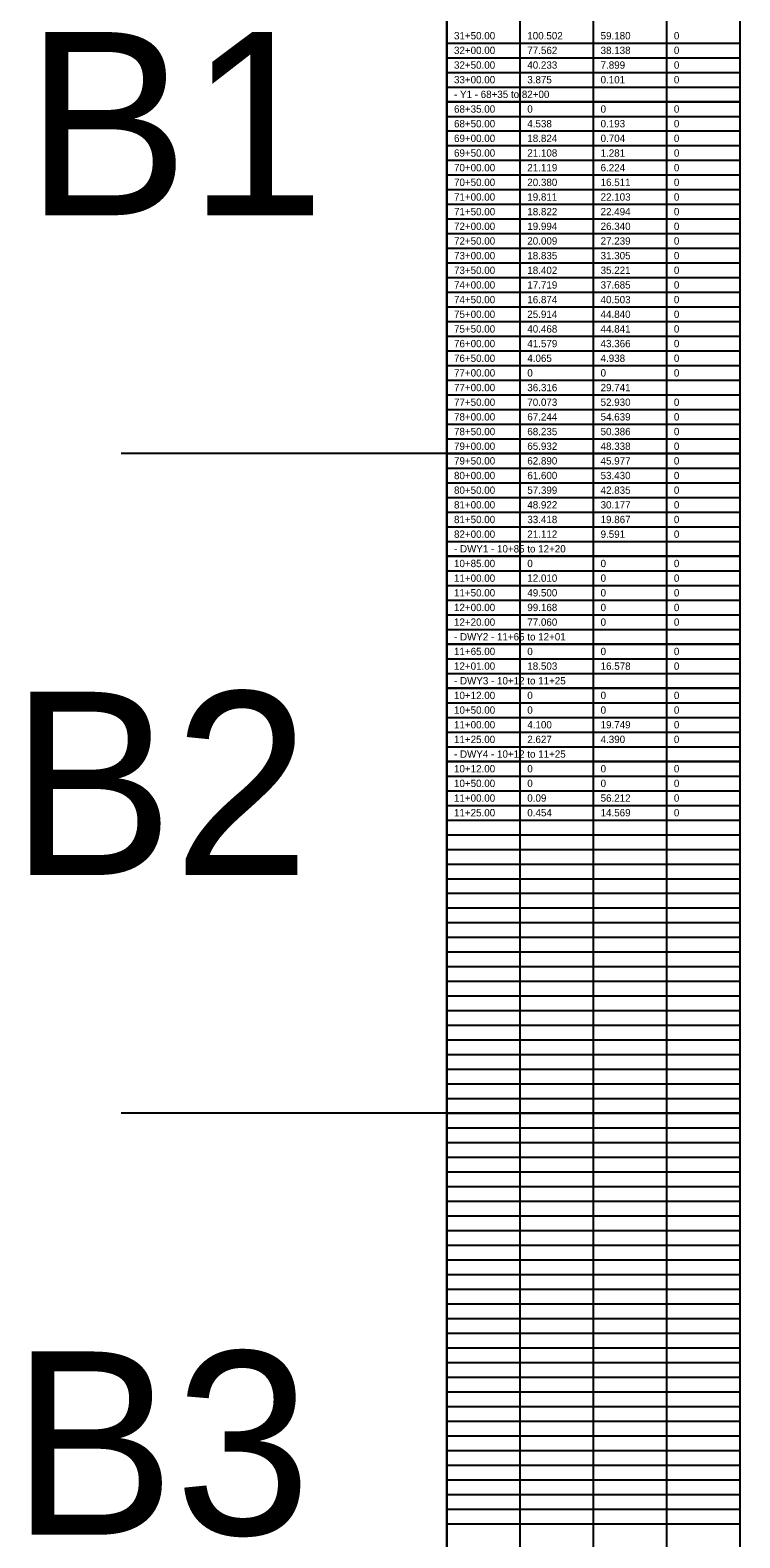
# Model space of a CAD drawing. Extents: x -124 to 80, y -10800 to 19.
# Drawn here: x -113.7 to 80, y -1195.9 to -784.5 of the extents above; entities that cross this region are included whole.
import ezdxf

# ---------------------------------------------------------------- set-up
doc = ezdxf.new("R2010")
doc.units = 0
for name, color, linetype in [('Prop Shade Light', 7, 'Continuous'), ('Prop XSC Text', 7, 'Continuous'), ('Scratch_Level_1', 7, 'Continuous'), ('Scratch_Level_3', 7, 'Continuous'), ('Sheet Clip Boundary CELL', 7, 'Continuous')]:
    doc.layers.add(name, color=color, linetype=linetype)

msp = doc.modelspace()

# ---------------------------------------------------------------- linework, layer by layer
at = {"layer": 'Prop Shade Light'}
for points in [[(0, -800), (80, -800), (80, -804), (0, -804)], [(0, -924), (80, -924), (80, -928), (0, -928)], [(0, -948), (80, -948), (80, -952), (0, -952)], [(0, -960), (80, -960), (80, -964), (0, -964)], [(0, -980), (80, -980), (80, -984), (0, -984)]]:
    msp.add_lwpolyline(points, close=True, dxfattribs=at)
at = {"layer": 'Scratch_Level_1'}
for p, q in [((0, 0), (0, -6480)), ((20, 0), (20, -6480)), ((40, 0), (40, -6480)), ((60, 0), (60, -6480)), ((80, 0), (80, -6480)), ((0, -788), (80, -788)), ((0, -792), (80, -792)), ((0, -796), (80, -796)), ((0, -800), (80, -800)), ((0, -804), (80, -804)), ((0, -808), (80, -808)), ((0, -812), (80, -812)), ((0, -816), (80, -816)), ((0, -820), (80, -820)), ((0, -824), (80, -824)), ((0, -828), (80, -828)), ((0, -832), (80, -832)), ((0, -836), (80, -836)), ((0, -840), (80, -840)), ((0, -844), (80, -844)), ((0, -848), (80, -848)), ((0, -852), (80, -852)), ((0, -856), (80, -856)), ((0, -860), (80, -860)), ((0, -864), (80, -864)), ((0, -868), (80, -868)), ((0, -872), (80, -872)), ((0, -876), (80, -876)), ((0, -880), (80, -880)), ((0, -884), (80, -884)), ((0, -888), (80, -888)), ((0, -892), (80, -892)), ((0, -896), (80, -896)), ((0, -900), (-88.81, -900)), ((0, -900), (80, -900)), ((0, -904), (80, -904)), ((0, -908), (80, -908)), ((0, -912), (80, -912)), ((0, -916), (80, -916)), ((0, -920), (80, -920)), ((0, -924), (80, -924)), ((0, -928), (80, -928)), ((0, -932), (80, -932)), ((0, -936), (80, -936)), ((0, -940), (80, -940)), ((0, -944), (80, -944)), ((0, -948), (80, -948)), ((0, -952), (80, -952)), ((0, -956), (80, -956)), ((0, -960), (80, -960)), ((0, -964), (80, -964)), ((0, -968), (80, -968)), ((0, -972), (80, -972)), ((0, -976), (80, -976)), ((0, -980), (80, -980)), ((0, -984), (80, -984)), ((0, -988), (80, -988)), ((0, -992), (80, -992)), ((0, -996), (80, -996)), ((0, -1000), (80, -1000)), ((0, -1004), (80, -1004)), ((0, -1008), (80, -1008)), ((0, -1012), (80, -1012)), ((0, -1016), (80, -1016)), ((0, -1020), (80, -1020)), ((0, -1024), (80, -1024)), ((0, -1028), (80, -1028)), ((0, -1032), (80, -1032)), ((0, -1036), (80, -1036)), ((0, -1040), (80, -1040)), ((0, -1044), (80, -1044)), ((0, -1048), (80, -1048)), ((0, -1052), (80, -1052)), ((0, -1056), (80, -1056)), ((0, -1060), (80, -1060)), ((0, -1064), (80, -1064)), ((0, -1068), (80, -1068)), ((0, -1072), (80, -1072)), ((0, -1076), (80, -1076)), ((0, -1080), (-88.81, -1080)), ((0, -1080), (80, -1080)), ((0, -1084), (80, -1084)), ((0, -1088), (80, -1088)), ((0, -1092), (80, -1092)), ((0, -1096), (80, -1096)), ((0, -1100), (80, -1100)), ((0, -1104), (80, -1104)), ((0, -1108), (80, -1108)), ((0, -1112), (80, -1112)), ((0, -1116), (80, -1116)), ((0, -1120), (80, -1120)), ((0, -1124), (80, -1124)), ((0, -1128), (80, -1128)), ((0, -1132), (80, -1132)), ((0, -1136), (80, -1136)), ((0, -1140), (80, -1140)), ((0, -1144), (80, -1144)), ((0, -1148), (80, -1148)), ((0, -1152), (80, -1152)), ((0, -1156), (80, -1156)), ((0, -1160), (80, -1160)), ((0, -1164), (80, -1164)), ((0, -1168), (80, -1168)), ((0, -1172), (80, -1172)), ((0, -1176), (80, -1176)), ((0, -1180), (80, -1180)), ((0, -1184), (80, -1184)), ((0, -1188), (80, -1188)), ((0, -1192), (80, -1192))]:
    msp.add_line(p, q, dxfattribs=at)
at = {"layer": 'Sheet Clip Boundary CELL'}
for points in [[(0, -720), (80, -720), (80, -900), (0, -900)], [(0, -900), (80, -900), (80, -1080), (0, -1080)], [(0, -1080), (80, -1080), (80, -1260), (0, -1260)]]:
    msp.add_lwpolyline(points, close=True, dxfattribs=at)

# ---------------------------------------------------------------- texts
at = {"layer": 'Prop XSC Text'}
for s, p in [('31+50.00', (2, -787)), ('100.502', (22, -787)), ('59.180', (42, -787)), ('0', (62, -787)), ('32+00.00', (2, -791)), ('77.562', (22, -791)), ('38.138', (42, -791)), ('0', (62, -791)), ('32+50.00', (2, -795)), ('40.233', (22, -795)), ('7.899', (42, -795)), ('0', (62, -795)), ('33+00.00', (2, -799)), ('3.875', (22, -799)), ('0.101', (42, -799)), ('0', (62, -799)), ('- Y1 - 68+35 to 82+00', (2, -803)), ('68+35.00', (2, -807)), ('0', (22, -807)), ('0', (42, -807)), ('0', (62, -807)), ('68+50.00', (2, -811)), ('4.538', (22, -811)), ('0.193', (42, -811)), ('0', (62, -811)), ('69+00.00', (2, -815)), ('18.824', (22, -815)), ('0.704', (42, -815)), ('0', (62, -815)), ('69+50.00', (2, -819)), ('21.108', (22, -819)), ('1.281', (42, -819)), ('0', (62, -819)), ('70+00.00', (2, -823)), ('21.119', (22, -823)), ('6.224', (42, -823)), ('0', (62, -823)), ('70+50.00', (2, -827)), ('20.380', (22, -827)), ('16.511', (42, -827)), ('0', (62, -827)), ('71+00.00', (2, -831)), ('19.811', (22, -831)), ('22.103', (42, -831)), ('0', (62, -831)), ('71+50.00', (2, -835)), ('18.822', (22, -835)), ('22.494', (42, -835)), ('0', (62, -835)), ('72+00.00', (2, -839)), ('19.994', (22, -839)), ('26.340', (42, -839)), ('0', (62, -839)), ('72+50.00', (2, -843)), ('20.009', (22, -843)), ('27.239', (42, -843)), ('0', (62, -843)), ('73+00.00', (2, -847)), ('18.835', (22, -847)), ('31.305', (42, -847)), ('0', (62, -847)), ('73+50.00', (2, -851)), ('18.402', (22, -851)), ('35.221', (42, -851)), ('0', (62, -851)), ('74+00.00', (2, -855)), ('17.719', (22, -855)), ('37.685', (42, -855)), ('0', (62, -855)), ('74+50.00', (2, -859)), ('16.874', (22, -859)), ('40.503', (42, -859)), ('0', (62, -859)), ('75+00.00', (2, -863)), ('25.914', (22, -863)), ('44.840', (42, -863)), ('0', (62, -863)), ('75+50.00', (2, -867)), ('40.468', (22, -867)), ('44.841', (42, -867)), ('0', (62, -867)), ('76+00.00', (2, -871)), ('41.579', (22, -871)), ('43.366', (42, -871)), ('0', (62, -871)), ('76+50.00', (2, -875)), ('4.065', (22, -875)), ('4.938', (42, -875)), ('0', (62, -875)), ('77+00.00', (2, -879)), ('0', (22, -879)), ('0', (42, -879)), ('0', (62, -879)), ('77+00.00', (2, -883)), ('36.316', (22, -883)), ('29.741', (42, -883)), ('77+50.00', (2, -887)), ('70.073', (22, -887)), ('52.930', (42, -887)), ('0', (62, -887)), ('78+00.00', (2, -891)), ('67.244', (22, -891)), ('54.639', (42, -891)), ('0', (62, -891)), ('78+50.00', (2, -895)), ('68.235', (22, -895)), ('50.386', (42, -895)), ('0', (62, -895)), ('79+00.00', (2, -899)), ('65.932', (22, -899)), ('48.338', (42, -899)), ('0', (62, -899)), ('80+00.00', (2, -907)), ('79+50.00', (2, -903)), ('62.890', (22, -903)), ('61.600', (22, -907)), ('45.977', (42, -903)), ('53.430', (42, -907)), ('0', (62, -903)), ('0', (62, -907)), ('80+50.00', (2, -911)), ('57.399', (22, -911)), ('42.835', (42, -911)), ('0', (62, -911)), ('81+00.00', (2, -915)), ('48.922', (22, -915)), ('30.177', (42, -915)), ('0', (62, -915)), ('81+50.00', (2, -919)), ('33.418', (22, -919)), ('19.867', (42, -919)), ('0', (62, -919)), ('82+00.00', (2, -923)), ('21.112', (22, -923)), ('9.591', (42, -923)), ('0', (62, -923)), ('- DWY1 - 10+85 to 12+20 ', (2, -927)), ('10+85.00', (2, -931)), ('0', (22, -931)), ('0', (42, -931)), ('0', (62, -931)), ('11+00.00', (2, -935)), ('12.010', (22, -935)), ('0', (42, -935)), ('0', (62, -935)), ('11+50.00', (2, -939)), ('49.500', (22, -939)), ('0', (42, -939)), ('0', (62, -939)), ('12+00.00', (2, -943)), ('99.168', (22, -943)), ('0', (42, -943)), ('0', (62, -943)), ('12+20.00', (2, -947)), ('77.060', (22, -947)), ('0', (42, -947)), ('0', (62, -947)), ('- DWY2 - 11+65 to 12+01 ', (2, -951)), ('11+65.00', (2, -955)), ('0', (22, -955)), ('0', (42, -955)), ('0', (62, -955)), ('12+01.00', (2, -959)), ('18.503', (22, -959)), ('16.578', (42, -959)), ('0', (62, -959)), ('- DWY3 - 10+12 to 11+25', (2, -963)), ('10+12.00', (2, -967)), ('0', (22, -967)), ('0', (42, -967)), ('0', (62, -967)), ('10+50.00', (2, -971)), ('0', (22, -971)), ('0', (42, -971)), ('0', (62, -971)), ('11+00.00', (2, -975)), ('4.100', (22, -975)), ('19.749', (42, -975)), ('0', (62, -975)), ('11+25.00', (2, -979)), ('2.627', (22, -979)), ('4.390', (42, -979)), ('0', (62, -979)), ('- DWY4 - 10+12 to 11+25 ', (2, -983)), ('10+12.00', (2, -987)), ('0', (22, -987)), ('0', (42, -987)), ('0', (62, -987)), ('10+50.00', (2, -991)), ('0', (22, -991)), ('0', (42, -991)), ('0', (62, -991)), ('11+00.00', (2, -995)), ('0.09', (22, -995)), ('56.212', (42, -995)), ('0', (62, -995)), ('11+25.00', (2, -999)), ('0.454', (22, -999)), ('14.569', (42, -999)), ('0', (62, -999))]:
    msp.add_text(s, height=2, dxfattribs=at).set_placement(p)
at = {"layer": 'Scratch_Level_3'}
for s, p in [('B1', (-114.99, -835)), ('B2', (-119.15, -1015)), ('B3', (-118.78, -1195))]:
    msp.add_text(s, height=50, dxfattribs=at).set_placement(p)

doc.saveas('drawing.dxf')
